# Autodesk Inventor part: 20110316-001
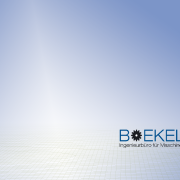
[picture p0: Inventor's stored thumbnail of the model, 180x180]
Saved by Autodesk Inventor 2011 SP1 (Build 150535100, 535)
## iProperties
Created: 2011-03
Part Number: 20110316-001
Material: Standard
Document SubType Name: Blech
Designer: Boekels
Density: 1 g/cm^3
Sheet Metal Rule: Standard_mm
Author: Boekels
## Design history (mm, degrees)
node "Fläche1"
  sketch "Skizze1"
    geometry: L1 (-100, 150)-(100, 150); L2 (100, 150)-(100, -150); L3 (100, -150)-(-100, -150); L4 (-100, -150)-(-100, 150); 3 further points
    constraints: 8 end point, 2 midpoint, 2 parallel, 1 horizontal, 1 horizontal alignment, 1 perpendicular, 1 vertical alignment
    dimensions: "d0" = 300 distance of L1.end L2.end; "d1" = 200 distance of L1.start L1.end
node "Konturlasche1"
  sketch "Skizze2"
    geometry: L1 (100, 0.5)-(145.899, 80); L2 (100, 0.5)-(191.799, 0.5); L3 (145.899, 80)-(162.899, 80); L4 (162.899, 80)-(162.899, 65); L5 (-100, 0)-(100, 0) reference; 1 further point
    constraints: 8 end point, 2 horizontal, 1 equal length, 1 perpendicular
    dimensions: "d3" = 60 deg angle of L2 L1; "d4" = 17 distance of L1.end L3.end; "d5" = 15 distance of L3.end L4.end; "d6" = 80 distance between parallel lines of L5 L3
node "Volumenkörper1"
node "Volumenkörpern"
node "Oberflächenkörpern"
feature "Grobblech1" dims "Stärke" = 0.5 (derived)
feature "Grobblech2" dims "d7" = 0.5 (= BreiteBiegungsfreistellung), "d8" = 0.25 (= TiefeBiegungsfreistellung), "d9" = 1 (= MinimalRest), "d10" = 0.5 (= Biegeradius), "d11" = 0.5 (= Biegeradius), "d12" = 0.5, "d13" = 2 (= GrößeEckenfreistellung), "d14" = 0.01, "d15" = 0.5 (= JacobiRadiusGröße), "Stärke" = 0.5 (derived), "AbstandVerbindung" = 0.01
feature "Biegung1" dims "d7" = 0.5 (= BreiteBiegungsfreistellung), "d8" = 0.25 (= TiefeBiegungsfreistellung), "d9" = 1 (= MinimalRest), "d10" = 0.5 (= Biegeradius), "d11" = 0.5 (= Biegeradius), "d12" = 0.5, "Stärke" = 0.5 (derived), "AbstandVerbindung" = 0.01
feature "Ecke1" dims "d12" = 0.5, "d13" = 2 (= GrößeEckenfreistellung), "d14" = 0.01, "d15" = 0.5 (= JacobiRadiusGröße)
other parameters: "KFaktor" = 4.4, "Biegeradius" = 0.5 (= Stärke), "BreiteBiegungsfreistellung" = 0.5 (= Stärke), "TiefeBiegungsfreistellung" = 0.25 (= 0.5 x Stärke), "GrößeEckenfreistellung" = 2 (= 4 x Stärke), "MinimalRest" = 1 (= 2 x Stärke), "Übergangsradius" = 0.5 (= Biegeradius), "JacobiRadiusGröße" = 0.5 (= Biegeradius), "Abstandsgröße" = 0.5 (= Stärke), "d2" = 0.5 (= Biegeradius)
